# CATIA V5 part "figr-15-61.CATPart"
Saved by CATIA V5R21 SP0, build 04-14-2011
Part number: Part1
Bounding box of the stored display mesh (mm): x -56.905 to 119.887, y -33.101 to 33.101, z 0 to 1
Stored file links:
  D:\CATIA V5R21 E-RESOURCES\CATIA-V5R21\catia-v5r21-prt\c15-catia-v5r20-prt\c15-catia-v5r21-figr-15-61.CATPart
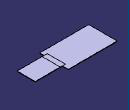
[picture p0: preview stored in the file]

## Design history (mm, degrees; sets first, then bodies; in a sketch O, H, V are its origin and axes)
SheetMetalParameters1: Thickness 1, BendRadius 7, KFactor 0.5 {= log(min(100,max(20*SheetMetalParameters1.BendRadius,SheetMetalParameters1.Thickness)/SheetMetalParameters1.Thickness))/log(100)/2}, ReliefRadialLength 1, ReliefAxialLength 2, MinimumBendRadius 0
Body1 (main body)
  Sketch1 on xy-plane, origin (0, 0, 0), H (1, 0, 0), V (0, 1, 0)
    line L1 (-56.9047, 33.1006) -> (56.9047, 33.1006)
    line L2 (56.9047, 33.1006) -> (56.9047, -33.1006)
    line L3 (56.9047, -33.1006) -> (-56.9047, -33.1006)
    line L4 (-56.9047, -33.1006) -> (-56.9047, 33.1006)
    horizontal: L1 H, L3 H
    vertical: L2 V, L4 V
    symmetry: L1 L3 H, L4 L2 V
  Wall1: Thickness 1, Profile Sketch1
  d_NewWallOnEdge1: NewWallOnEdge_Edge edge [face of Wall1 | face of Wall1], NewWallOnEdge_Length 66.2011, NewWallOnEdge_HeightLimitOffset 0, NewWallOnEdge_WidthOffset1 -10, NewWallOnEdge_WidthOffset2 -14, NewWallOnEdge_Angle 90, NewWallOnEdge_BendRadiusValue 7 {= SheetMetalParameters1.BendRadius}, NewWallOnEdge_BendTable SheetMetalParameters1, KFacteur 0.5 {= log(min(100,max(20*d_NewWallOnEdge1.Radius,SheetMetalParameters1.Thickness)/SheetMetalParameters1.Thickness))/log(100)/2}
